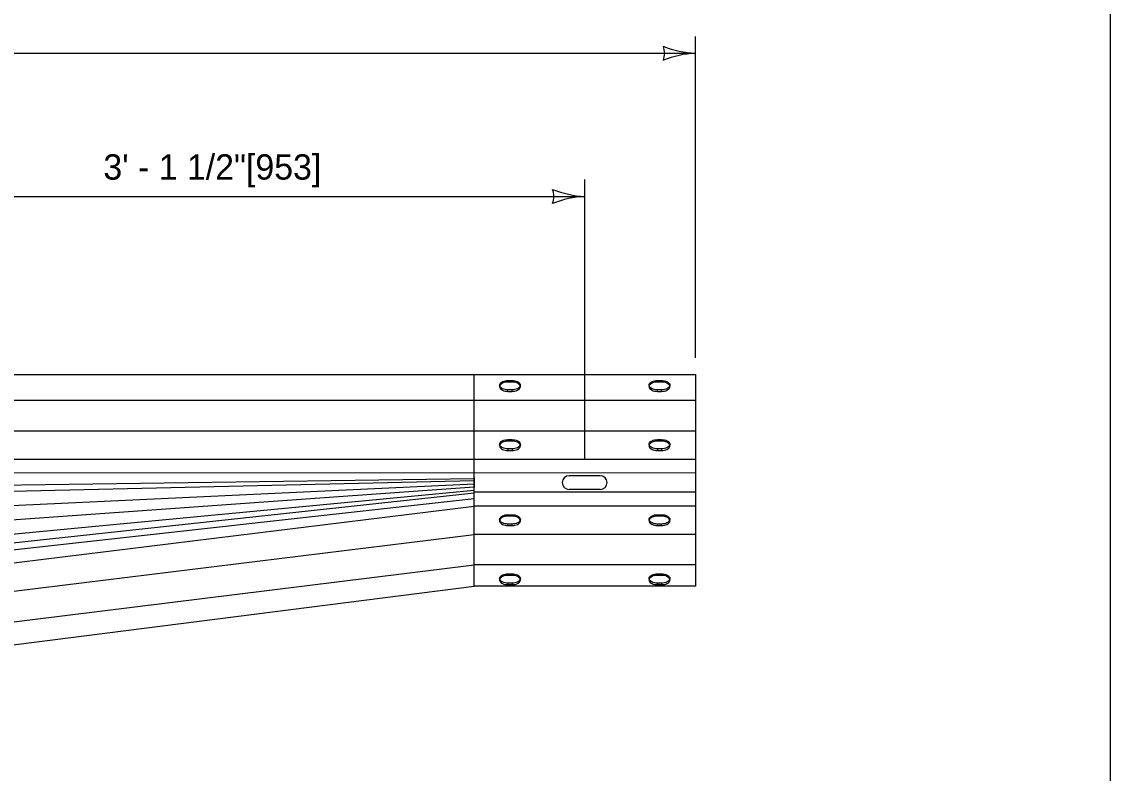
# Model space of a CAD drawing. Extents: x 49991 to 50160, y 49948 to 50051.
# Drawn here: x 50014.17 to 50016.75, y 49992.536 to 49994.318 of the extents above; entities that cross this region are included whole.
import ezdxf

# ---------------------------------------------------------------- set-up
doc = ezdxf.new("R2010")
doc.units = 0
for name, color, linetype in [('Level 1', 7, 'Continuous'), ('Level 2', 7, 'Continuous'), ('Level 3', 7, 'Continuous')]:
    doc.layers.add(name, color=color, linetype=linetype)

msp = doc.modelspace()

# ---------------------------------------------------------------- linework, layer by layer
at = {"layer": 'Level 1'}
for p, q in [((50012.234, 49993.4814), (50015.7668, 49993.4812)), ((50015.2419, 49992.9795), (50015.2419, 49993.4812)), ((50015.7668, 49993.4812), (50015.7668, 49993.4738)), ((50015.3025, 49993.4563), (50015.3025, 49993.4527)), ((50015.3222, 49993.4673), (50015.3321, 49993.4673)), ((50015.3222, 49993.4637), (50015.3222, 49993.4673)), ((50015.3321, 49993.4637), (50015.3222, 49993.4637)), ((50015.3321, 49993.4637), (50015.3321, 49993.4673)), ((50015.3518, 49993.4527), (50015.3518, 49993.4563)), ((50015.6569, 49993.4563), (50015.6569, 49993.4527)), ((50015.6766, 49993.4637), (50015.6766, 49993.4673)), ((50015.6766, 49993.4673), (50015.6864, 49993.4673)), ((50015.6864, 49993.4637), (50015.6766, 49993.4637)), ((50015.6864, 49993.4637), (50015.6864, 49993.4673)), ((50015.7061, 49993.4527), (50015.7061, 49993.4563)), ((50015.7668, 49993.4738), (50015.7668, 49993.471)), ((50015.7668, 49993.471), (50015.7668, 49993.4206)), ((50015.3321, 49993.4453), (50015.3222, 49993.4453)), ((50015.3222, 49993.4416), (50015.3222, 49993.4453)), ((50015.3222, 49993.4416), (50015.3321, 49993.4416)), ((50015.3321, 49993.4416), (50015.3321, 49993.4453)), ((50015.6864, 49993.4453), (50015.6766, 49993.4453)), ((50015.6766, 49993.4416), (50015.6766, 49993.4453)), ((50015.6766, 49993.4416), (50015.6864, 49993.4416)), ((50015.6864, 49993.4416), (50015.6864, 49993.4453)), ((50012.6417, 49993.4206), (50015.7668, 49993.4206)), ((50015.7668, 49993.4206), (50015.7668, 49993.3481)), ((50012.6417, 49993.3481), (50015.7668, 49993.3478)), ((50015.3222, 49993.3271), (50015.3321, 49993.3271)), ((50015.3222, 49993.3271), (50015.3222, 49993.3235)), ((50015.3321, 49993.3271), (50015.3321, 49993.3235)), ((50015.6766, 49993.3271), (50015.6864, 49993.3271)), ((50015.6766, 49993.3271), (50015.6766, 49993.3235)), ((50015.6864, 49993.3271), (50015.6864, 49993.3235)), ((50015.7668, 49993.3481), (50015.7668, 49993.2808)), ((50015.3025, 49993.3161), (50015.3025, 49993.3125)), ((50015.3321, 49993.3235), (50015.3222, 49993.3235)), ((50015.3222, 49993.3051), (50015.3222, 49993.3014)), ((50015.3321, 49993.3051), (50015.3222, 49993.3051)), ((50015.3222, 49993.3014), (50015.3321, 49993.3014)), ((50015.3321, 49993.3051), (50015.3321, 49993.3014)), ((50015.3518, 49993.3125), (50015.3518, 49993.3161)), ((50015.6569, 49993.3161), (50015.6569, 49993.3125)), ((50015.6864, 49993.3235), (50015.6766, 49993.3235)), ((50015.6766, 49993.3051), (50015.6766, 49993.3014)), ((50015.6864, 49993.3051), (50015.6766, 49993.3051)), ((50015.6766, 49993.3014), (50015.6864, 49993.3014)), ((50015.6864, 49993.3051), (50015.6864, 49993.3014)), ((50015.7061, 49993.3125), (50015.7061, 49993.3161)), ((50012.6417, 49993.2803), (50015.7668, 49993.2808)), ((50015.7668, 49993.2808), (50015.7668, 49993.2482)), ((50013.9811, 49993.2491), (50015.7668, 49993.2485)), ((50015.2419, 49993.2294), (50012.6417, 49993.1687)), ((50013.9757, 49993.2172), (50015.2419, 49993.2352)), ((50015.2419, 49993.2367), (50015.2419, 49993.2321)), ((50015.2419, 49993.2321), (50015.2419, 49993.2275)), ((50015.2419, 49993.2275), (50015.2419, 49993.223)), ((50015.2419, 49993.223), (50015.2419, 49993.2184)), ((50015.4674, 49993.2417), (50015.5412, 49993.2417)), ((50015.7668, 49993.2482), (50015.7668, 49993.2023)), ((50012.6417, 49993.1011), (50015.2419, 49993.2221)), ((50015.2419, 49993.2146), (50012.6417, 49993.0283)), ((50012.6417, 49992.9608), (50015.2419, 49993.2073)), ((50013.9883, 49993.0651), (50015.2419, 49993.201)), ((50015.2419, 49993.2184), (50015.2419, 49993.2138)), ((50015.7668, 49993.2023), (50015.2419, 49993.2023)), ((50015.5412, 49993.2088), (50015.4674, 49993.2088)), ((50015.7668, 49993.2023), (50015.7668, 49993.1697)), ((50013.9906, 49993.0485), (50015.2419, 49993.1879)), ((50012.6417, 49992.8492), (50015.2419, 49993.1697)), ((50015.7668, 49993.1697), (50015.2419, 49993.1697)), ((50015.3222, 49993.1491), (50015.3321, 49993.1491)), ((50015.3222, 49993.1454), (50015.3222, 49993.1491)), ((50015.3321, 49993.1454), (50015.3222, 49993.1454)), ((50015.3321, 49993.1454), (50015.3321, 49993.1491)), ((50015.6766, 49993.1491), (50015.6864, 49993.1491)), ((50015.6766, 49993.1454), (50015.6766, 49993.1491)), ((50015.6864, 49993.1454), (50015.6766, 49993.1454)), ((50015.6864, 49993.1454), (50015.6864, 49993.1491)), ((50015.7668, 49993.1697), (50015.7668, 49993.1024)), ((50015.3025, 49993.138), (50015.3025, 49993.1344)), ((50015.3321, 49993.127), (50015.3222, 49993.127)), ((50015.3222, 49993.1234), (50015.3222, 49993.127)), ((50015.3222, 49993.1234), (50015.3321, 49993.1234)), ((50015.3321, 49993.1234), (50015.3321, 49993.127)), ((50015.3518, 49993.1344), (50015.3518, 49993.138)), ((50015.6569, 49993.138), (50015.6569, 49993.1344)), ((50015.6864, 49993.127), (50015.6766, 49993.127)), ((50015.6766, 49993.1234), (50015.6766, 49993.127)), ((50015.6766, 49993.1234), (50015.6864, 49993.1234)), ((50015.6864, 49993.1234), (50015.6864, 49993.127)), ((50015.7061, 49993.1344), (50015.7061, 49993.138)), ((50012.6417, 49992.7816), (50015.2419, 49993.1024)), ((50015.7668, 49993.1024), (50015.2419, 49993.1024)), ((50015.7668, 49993.1024), (50015.7668, 49993.0299)), ((50012.6417, 49992.7088), (50015.2419, 49993.0299)), ((50015.7668, 49993.0299), (50015.2419, 49993.0299)), ((50015.7668, 49993.0299), (50015.7668, 49992.9795)), ((50015.3025, 49992.9978), (50015.3025, 49992.9942)), ((50015.3222, 49993.0089), (50015.3321, 49993.0089)), ((50015.3222, 49993.0089), (50015.3222, 49993.0052)), ((50015.3321, 49993.0052), (50015.3222, 49993.0052)), ((50015.3321, 49993.0089), (50015.3321, 49993.0052)), ((50015.3518, 49992.9942), (50015.3518, 49992.9978)), ((50015.6569, 49992.9978), (50015.6569, 49992.9942)), ((50015.6766, 49993.0089), (50015.6864, 49993.0089)), ((50015.6766, 49993.0089), (50015.6766, 49993.0052)), ((50015.6864, 49993.0052), (50015.6766, 49993.0052)), ((50015.6864, 49993.0089), (50015.6864, 49993.0052)), ((50015.7061, 49992.9942), (50015.7061, 49992.9978)), ((50012.6417, 49992.6481), (50015.2419, 49992.9795)), ((50015.7668, 49992.9795), (50015.2419, 49992.9795)), ((50015.3222, 49992.9868), (50015.3222, 49992.9832)), ((50015.3321, 49992.9868), (50015.3222, 49992.9868)), ((50015.3222, 49992.9832), (50015.3321, 49992.9832)), ((50015.3321, 49992.9868), (50015.3321, 49992.9832)), ((50015.6766, 49992.9868), (50015.6766, 49992.9832)), ((50015.6864, 49992.9868), (50015.6766, 49992.9868)), ((50015.6766, 49992.9832), (50015.6864, 49992.9832)), ((50015.6864, 49992.9868), (50015.6864, 49992.9832))]:
    msp.add_line(p, q, dxfattribs=at)
msp.add_lwpolyline([(49999.3835, 49998.9992), (50016.7501, 49998.9992), (50016.7501, 49987.7988), (49999.3835, 49987.7988)], close=True, dxfattribs=at)
for points in [[(50015.3222, 49993.4453), (50015.3188, 49993.4454), (50015.3155, 49993.4459), (50015.3124, 49993.4467), (50015.3096, 49993.4478), (50015.3072, 49993.4492), (50015.3052, 49993.4508), (50015.3037, 49993.4525), (50015.3028, 49993.4544), (50015.3025, 49993.4563), (50015.3028, 49993.4582), (50015.3037, 49993.4601), (50015.3052, 49993.4618), (50015.3072, 49993.4634), (50015.3096, 49993.4647), (50015.3124, 49993.4658), (50015.3155, 49993.4666), (50015.3188, 49993.4671), (50015.3222, 49993.4673)], [(50015.3222, 49993.4637), (50015.3188, 49993.4635), (50015.3155, 49993.463), (50015.3124, 49993.4622), (50015.3096, 49993.4611), (50015.3072, 49993.4597), (50015.3052, 49993.4582), (50015.3037, 49993.4564), (50015.3028, 49993.4546), (50015.3028, 49993.4545)], [(50015.3321, 49993.4673), (50015.3355, 49993.4671), (50015.3388, 49993.4666), (50015.3419, 49993.4658), (50015.3447, 49993.4647), (50015.3472, 49993.4634), (50015.3491, 49993.4618), (50015.3506, 49993.4601), (50015.3515, 49993.4582), (50015.3518, 49993.4563), (50015.3515, 49993.4544), (50015.3506, 49993.4525), (50015.3491, 49993.4508), (50015.3472, 49993.4492), (50015.3447, 49993.4478), (50015.3419, 49993.4467), (50015.3388, 49993.4459), (50015.3355, 49993.4454), (50015.3321, 49993.4453)], [(50015.3515, 49993.4545), (50015.3515, 49993.4546), (50015.3506, 49993.4564), (50015.3491, 49993.4582), (50015.3472, 49993.4597), (50015.3447, 49993.4611), (50015.3419, 49993.4622), (50015.3388, 49993.463), (50015.3355, 49993.4635), (50015.3321, 49993.4637)], [(50015.6766, 49993.4453), (50015.6731, 49993.4454), (50015.6698, 49993.4459), (50015.6667, 49993.4467), (50015.6639, 49993.4478), (50015.6615, 49993.4492), (50015.6595, 49993.4508), (50015.6581, 49993.4525), (50015.6572, 49993.4544), (50015.6569, 49993.4563), (50015.6572, 49993.4582), (50015.6581, 49993.4601), (50015.6595, 49993.4618), (50015.6615, 49993.4634), (50015.6639, 49993.4647), (50015.6667, 49993.4658), (50015.6698, 49993.4666), (50015.6731, 49993.4671), (50015.6766, 49993.4673)], [(50015.6766, 49993.4637), (50015.6731, 49993.4635), (50015.6698, 49993.463), (50015.6667, 49993.4622), (50015.6639, 49993.4611), (50015.6615, 49993.4597), (50015.6595, 49993.4582), (50015.6581, 49993.4564), (50015.6572, 49993.4546), (50015.6571, 49993.4545)], [(50015.6864, 49993.4673), (50015.6898, 49993.4671), (50015.6931, 49993.4666), (50015.6963, 49993.4658), (50015.6991, 49993.4647), (50015.7015, 49993.4634), (50015.7035, 49993.4618), (50015.7049, 49993.4601), (50015.7058, 49993.4582), (50015.7061, 49993.4563), (50015.7058, 49993.4544), (50015.7049, 49993.4525), (50015.7035, 49993.4508), (50015.7015, 49993.4492), (50015.6991, 49993.4478), (50015.6963, 49993.4467), (50015.6931, 49993.4459), (50015.6898, 49993.4454), (50015.6864, 49993.4453)], [(50015.7058, 49993.4545), (50015.7058, 49993.4546), (50015.7049, 49993.4564), (50015.7035, 49993.4582), (50015.7015, 49993.4597), (50015.6991, 49993.4611), (50015.6963, 49993.4622), (50015.6931, 49993.463), (50015.6898, 49993.4635), (50015.6864, 49993.4637)], [(50015.3028, 49993.4545), (50015.3025, 49993.4527), (50015.3028, 49993.4507), (50015.3037, 49993.4489), (50015.3052, 49993.4471), (50015.3072, 49993.4456), (50015.3096, 49993.4442), (50015.3124, 49993.4431), (50015.3155, 49993.4423), (50015.3188, 49993.4418), (50015.3222, 49993.4416)], [(50015.3321, 49993.4416), (50015.3355, 49993.4418), (50015.3388, 49993.4423), (50015.3419, 49993.4431), (50015.3447, 49993.4442), (50015.3472, 49993.4456), (50015.3491, 49993.4471), (50015.3506, 49993.4489), (50015.3515, 49993.4507), (50015.3518, 49993.4527), (50015.3515, 49993.4545)], [(50015.6571, 49993.4545), (50015.6569, 49993.4527), (50015.6572, 49993.4507), (50015.6581, 49993.4489), (50015.6595, 49993.4471), (50015.6615, 49993.4456), (50015.6639, 49993.4442), (50015.6667, 49993.4431), (50015.6698, 49993.4423), (50015.6731, 49993.4418), (50015.6766, 49993.4416)], [(50015.6864, 49993.4416), (50015.6898, 49993.4418), (50015.6931, 49993.4423), (50015.6963, 49993.4431), (50015.6991, 49993.4442), (50015.7015, 49993.4456), (50015.7035, 49993.4471), (50015.7049, 49993.4489), (50015.7058, 49993.4507), (50015.7061, 49993.4527), (50015.7058, 49993.4545)], [(50015.3028, 49993.3143), (50015.3025, 49993.3161), (50015.3028, 49993.318), (50015.3037, 49993.3199), (50015.3052, 49993.3216), (50015.3072, 49993.3232), (50015.3096, 49993.3245), (50015.3124, 49993.3256), (50015.3155, 49993.3264), (50015.3188, 49993.3269), (50015.3222, 49993.3271)], [(50015.3321, 49993.3271), (50015.3355, 49993.3269), (50015.3388, 49993.3264), (50015.3419, 49993.3256), (50015.3447, 49993.3245), (50015.3472, 49993.3232), (50015.3491, 49993.3216), (50015.3506, 49993.3199), (50015.3515, 49993.318), (50015.3518, 49993.3161), (50015.3515, 49993.3143)], [(50015.6571, 49993.3143), (50015.6569, 49993.3161), (50015.6572, 49993.318), (50015.6581, 49993.3199), (50015.6595, 49993.3216), (50015.6615, 49993.3232), (50015.6639, 49993.3245), (50015.6667, 49993.3256), (50015.6698, 49993.3264), (50015.6731, 49993.3269), (50015.6766, 49993.3271)], [(50015.6864, 49993.3271), (50015.6898, 49993.3269), (50015.6931, 49993.3264), (50015.6963, 49993.3256), (50015.6991, 49993.3245), (50015.7015, 49993.3232), (50015.7035, 49993.3216), (50015.7049, 49993.3199), (50015.7058, 49993.318), (50015.7061, 49993.3161), (50015.7058, 49993.3143)], [(50015.3222, 49993.3235), (50015.3188, 49993.3233), (50015.3155, 49993.3228), (50015.3124, 49993.322), (50015.3096, 49993.3209), (50015.3072, 49993.3195), (50015.3052, 49993.318), (50015.3037, 49993.3162), (50015.3028, 49993.3144), (50015.3025, 49993.3125), (50015.3028, 49993.3105), (50015.3037, 49993.3087), (50015.3052, 49993.3069), (50015.3072, 49993.3054), (50015.3096, 49993.304), (50015.3124, 49993.3029), (50015.3155, 49993.3021), (50015.3188, 49993.3016), (50015.3222, 49993.3014)], [(50015.3222, 49993.3051), (50015.3188, 49993.3052), (50015.3155, 49993.3057), (50015.3124, 49993.3065), (50015.3096, 49993.3076), (50015.3072, 49993.309), (50015.3052, 49993.3106), (50015.3037, 49993.3123), (50015.3028, 49993.3142), (50015.3028, 49993.3143)], [(50015.3321, 49993.3014), (50015.3355, 49993.3016), (50015.3388, 49993.3021), (50015.3419, 49993.3029), (50015.3447, 49993.304), (50015.3472, 49993.3054), (50015.3491, 49993.3069), (50015.3506, 49993.3087), (50015.3515, 49993.3105), (50015.3518, 49993.3125), (50015.3515, 49993.3144), (50015.3506, 49993.3162), (50015.3491, 49993.318), (50015.3472, 49993.3195), (50015.3447, 49993.3209), (50015.3419, 49993.322), (50015.3388, 49993.3228), (50015.3355, 49993.3233), (50015.3321, 49993.3235)], [(50015.3515, 49993.3143), (50015.3515, 49993.3142), (50015.3506, 49993.3123), (50015.3491, 49993.3106), (50015.3472, 49993.309), (50015.3447, 49993.3076), (50015.3419, 49993.3065), (50015.3388, 49993.3057), (50015.3355, 49993.3052), (50015.3321, 49993.3051)], [(50015.6766, 49993.3235), (50015.6731, 49993.3233), (50015.6698, 49993.3228), (50015.6667, 49993.322), (50015.6639, 49993.3209), (50015.6615, 49993.3195), (50015.6595, 49993.318), (50015.6581, 49993.3162), (50015.6572, 49993.3144), (50015.6569, 49993.3125), (50015.6572, 49993.3105), (50015.6581, 49993.3087), (50015.6595, 49993.3069), (50015.6615, 49993.3054), (50015.6639, 49993.304), (50015.6667, 49993.3029), (50015.6698, 49993.3021), (50015.6731, 49993.3016), (50015.6766, 49993.3014)], [(50015.6766, 49993.3051), (50015.6731, 49993.3052), (50015.6698, 49993.3057), (50015.6667, 49993.3065), (50015.6639, 49993.3076), (50015.6615, 49993.309), (50015.6595, 49993.3106), (50015.6581, 49993.3123), (50015.6572, 49993.3142), (50015.6571, 49993.3143)], [(50015.6864, 49993.3014), (50015.6898, 49993.3016), (50015.6931, 49993.3021), (50015.6963, 49993.3029), (50015.6991, 49993.304), (50015.7015, 49993.3054), (50015.7035, 49993.3069), (50015.7049, 49993.3087), (50015.7058, 49993.3105), (50015.7061, 49993.3125), (50015.7058, 49993.3144), (50015.7049, 49993.3162), (50015.7035, 49993.318), (50015.7015, 49993.3195), (50015.6991, 49993.3209), (50015.6963, 49993.322), (50015.6931, 49993.3228), (50015.6898, 49993.3233), (50015.6864, 49993.3235)], [(50015.7058, 49993.3143), (50015.7058, 49993.3142), (50015.7049, 49993.3123), (50015.7035, 49993.3106), (50015.7015, 49993.309), (50015.6991, 49993.3076), (50015.6963, 49993.3065), (50015.6931, 49993.3057), (50015.6898, 49993.3052), (50015.6864, 49993.3051)], [(50015.3222, 49993.127), (50015.3188, 49993.1272), (50015.3155, 49993.1277), (50015.3124, 49993.1285), (50015.3096, 49993.1296), (50015.3072, 49993.131), (50015.3052, 49993.1325), (50015.3037, 49993.1343), (50015.3028, 49993.1361), (50015.3025, 49993.138), (50015.3028, 49993.14), (50015.3037, 49993.1418), (50015.3052, 49993.1436), (50015.3072, 49993.1451), (50015.3096, 49993.1465), (50015.3124, 49993.1476), (50015.3155, 49993.1484), (50015.3188, 49993.1489), (50015.3222, 49993.1491)], [(50015.3222, 49993.1454), (50015.3188, 49993.1453), (50015.3155, 49993.1448), (50015.3124, 49993.144), (50015.3096, 49993.1429), (50015.3072, 49993.1415), (50015.3052, 49993.1399), (50015.3037, 49993.1382), (50015.3028, 49993.1363), (50015.3028, 49993.1362)], [(50015.3321, 49993.1491), (50015.3355, 49993.1489), (50015.3388, 49993.1484), (50015.3419, 49993.1476), (50015.3447, 49993.1465), (50015.3472, 49993.1451), (50015.3491, 49993.1436), (50015.3506, 49993.1418), (50015.3515, 49993.14), (50015.3518, 49993.138), (50015.3515, 49993.1361), (50015.3506, 49993.1343), (50015.3491, 49993.1325), (50015.3472, 49993.131), (50015.3447, 49993.1296), (50015.3419, 49993.1285), (50015.3388, 49993.1277), (50015.3355, 49993.1272), (50015.3321, 49993.127)], [(50015.3515, 49993.1362), (50015.3515, 49993.1363), (50015.3506, 49993.1382), (50015.3491, 49993.1399), (50015.3472, 49993.1415), (50015.3447, 49993.1429), (50015.3419, 49993.144), (50015.3388, 49993.1448), (50015.3355, 49993.1453), (50015.3321, 49993.1454)], [(50015.6766, 49993.127), (50015.6731, 49993.1272), (50015.6698, 49993.1277), (50015.6667, 49993.1285), (50015.6639, 49993.1296), (50015.6615, 49993.131), (50015.6595, 49993.1325), (50015.6581, 49993.1343), (50015.6572, 49993.1361), (50015.6569, 49993.138), (50015.6572, 49993.14), (50015.6581, 49993.1418), (50015.6595, 49993.1436), (50015.6615, 49993.1451), (50015.6639, 49993.1465), (50015.6667, 49993.1476), (50015.6698, 49993.1484), (50015.6731, 49993.1489), (50015.6766, 49993.1491)], [(50015.6766, 49993.1454), (50015.6731, 49993.1453), (50015.6698, 49993.1448), (50015.6667, 49993.144), (50015.6639, 49993.1429), (50015.6615, 49993.1415), (50015.6595, 49993.1399), (50015.6581, 49993.1382), (50015.6572, 49993.1363), (50015.6571, 49993.1362)], [(50015.6864, 49993.1491), (50015.6898, 49993.1489), (50015.6931, 49993.1484), (50015.6963, 49993.1476), (50015.6991, 49993.1465), (50015.7015, 49993.1451), (50015.7035, 49993.1436), (50015.7049, 49993.1418), (50015.7058, 49993.14), (50015.7061, 49993.138), (50015.7058, 49993.1361), (50015.7049, 49993.1343), (50015.7035, 49993.1325), (50015.7015, 49993.131), (50015.6991, 49993.1296), (50015.6963, 49993.1285), (50015.6931, 49993.1277), (50015.6898, 49993.1272), (50015.6864, 49993.127)], [(50015.7058, 49993.1362), (50015.7058, 49993.1363), (50015.7049, 49993.1382), (50015.7035, 49993.1399), (50015.7015, 49993.1415), (50015.6991, 49993.1429), (50015.6963, 49993.144), (50015.6931, 49993.1448), (50015.6898, 49993.1453), (50015.6864, 49993.1454)], [(50015.3028, 49993.1362), (50015.3025, 49993.1344), (50015.3028, 49993.1325), (50015.3037, 49993.1306), (50015.3052, 49993.1289), (50015.3072, 49993.1273), (50015.3096, 49993.126), (50015.3124, 49993.1249), (50015.3155, 49993.1241), (50015.3188, 49993.1236), (50015.3222, 49993.1234)], [(50015.3321, 49993.1234), (50015.3355, 49993.1236), (50015.3388, 49993.1241), (50015.3419, 49993.1249), (50015.3447, 49993.126), (50015.3472, 49993.1273), (50015.3491, 49993.1289), (50015.3506, 49993.1306), (50015.3515, 49993.1325), (50015.3518, 49993.1344), (50015.3515, 49993.1362)], [(50015.6571, 49993.1362), (50015.6569, 49993.1344), (50015.6572, 49993.1325), (50015.6581, 49993.1306), (50015.6595, 49993.1289), (50015.6615, 49993.1273), (50015.6639, 49993.126), (50015.6667, 49993.1249), (50015.6698, 49993.1241), (50015.6731, 49993.1236), (50015.6766, 49993.1234)], [(50015.6864, 49993.1234), (50015.6898, 49993.1236), (50015.6931, 49993.1241), (50015.6963, 49993.1249), (50015.6991, 49993.126), (50015.7015, 49993.1273), (50015.7035, 49993.1289), (50015.7049, 49993.1306), (50015.7058, 49993.1325), (50015.7061, 49993.1344), (50015.7058, 49993.1362)], [(50015.3028, 49992.996), (50015.3025, 49992.9978), (50015.3028, 49992.9998), (50015.3037, 49993.0016), (50015.3052, 49993.0034), (50015.3072, 49993.0049), (50015.3096, 49993.0063), (50015.3124, 49993.0074), (50015.3155, 49993.0082), (50015.3188, 49993.0087), (50015.3222, 49993.0089)], [(50015.3222, 49993.0052), (50015.3188, 49993.0051), (50015.3155, 49993.0046), (50015.3124, 49993.0038), (50015.3096, 49993.0027), (50015.3072, 49993.0013), (50015.3052, 49992.9997), (50015.3037, 49992.998), (50015.3028, 49992.9961), (50015.3025, 49992.9942), (50015.3028, 49992.9923), (50015.3037, 49992.9904), (50015.3052, 49992.9887), (50015.3072, 49992.9871), (50015.3096, 49992.9858), (50015.3124, 49992.9847), (50015.3155, 49992.9839), (50015.3188, 49992.9834), (50015.3222, 49992.9832)], [(50015.3222, 49992.9868), (50015.3188, 49992.987), (50015.3155, 49992.9875), (50015.3124, 49992.9883), (50015.3096, 49992.9894), (50015.3072, 49992.9908), (50015.3052, 49992.9923), (50015.3037, 49992.9941), (50015.3028, 49992.9959), (50015.3028, 49992.996)], [(50015.3321, 49993.0089), (50015.3355, 49993.0087), (50015.3388, 49993.0082), (50015.3419, 49993.0074), (50015.3447, 49993.0063), (50015.3472, 49993.0049), (50015.3491, 49993.0034), (50015.3506, 49993.0016), (50015.3515, 49992.9998), (50015.3518, 49992.9978), (50015.3515, 49992.996)], [(50015.3321, 49992.9832), (50015.3355, 49992.9834), (50015.3388, 49992.9839), (50015.3419, 49992.9847), (50015.3447, 49992.9858), (50015.3472, 49992.9871), (50015.3491, 49992.9887), (50015.3506, 49992.9904), (50015.3515, 49992.9923), (50015.3518, 49992.9942), (50015.3515, 49992.9961), (50015.3506, 49992.998), (50015.3491, 49992.9997), (50015.3472, 49993.0013), (50015.3447, 49993.0027), (50015.3419, 49993.0038), (50015.3388, 49993.0046), (50015.3355, 49993.0051), (50015.3321, 49993.0052)], [(50015.3515, 49992.996), (50015.3515, 49992.9959), (50015.3506, 49992.9941), (50015.3491, 49992.9923), (50015.3472, 49992.9908), (50015.3447, 49992.9894), (50015.3419, 49992.9883), (50015.3388, 49992.9875), (50015.3355, 49992.987), (50015.3321, 49992.9868)], [(50015.6571, 49992.996), (50015.6569, 49992.9978), (50015.6572, 49992.9998), (50015.6581, 49993.0016), (50015.6595, 49993.0034), (50015.6615, 49993.0049), (50015.6639, 49993.0063), (50015.6667, 49993.0074), (50015.6698, 49993.0082), (50015.6731, 49993.0087), (50015.6766, 49993.0089)], [(50015.6766, 49993.0052), (50015.6731, 49993.0051), (50015.6698, 49993.0046), (50015.6667, 49993.0038), (50015.6639, 49993.0027), (50015.6615, 49993.0013), (50015.6595, 49992.9997), (50015.6581, 49992.998), (50015.6572, 49992.9961), (50015.6569, 49992.9942), (50015.6572, 49992.9923), (50015.6581, 49992.9904), (50015.6595, 49992.9887), (50015.6615, 49992.9871), (50015.6639, 49992.9858), (50015.6667, 49992.9847), (50015.6698, 49992.9839), (50015.6731, 49992.9834), (50015.6766, 49992.9832)], [(50015.6766, 49992.9868), (50015.6731, 49992.987), (50015.6698, 49992.9875), (50015.6667, 49992.9883), (50015.6639, 49992.9894), (50015.6615, 49992.9908), (50015.6595, 49992.9923), (50015.6581, 49992.9941), (50015.6572, 49992.9959), (50015.6571, 49992.996)], [(50015.6864, 49993.0089), (50015.6898, 49993.0087), (50015.6931, 49993.0082), (50015.6963, 49993.0074), (50015.6991, 49993.0063), (50015.7015, 49993.0049), (50015.7035, 49993.0034), (50015.7049, 49993.0016), (50015.7058, 49992.9998), (50015.7061, 49992.9978), (50015.7058, 49992.996)], [(50015.6864, 49992.9832), (50015.6898, 49992.9834), (50015.6931, 49992.9839), (50015.6963, 49992.9847), (50015.6991, 49992.9858), (50015.7015, 49992.9871), (50015.7035, 49992.9887), (50015.7049, 49992.9904), (50015.7058, 49992.9923), (50015.7061, 49992.9942), (50015.7058, 49992.9961), (50015.7049, 49992.998), (50015.7035, 49992.9997), (50015.7015, 49993.0013), (50015.6991, 49993.0027), (50015.6963, 49993.0038), (50015.6931, 49993.0046), (50015.6898, 49993.0051), (50015.6864, 49993.0052)], [(50015.7058, 49992.996), (50015.7058, 49992.9959), (50015.7049, 49992.9941), (50015.7035, 49992.9923), (50015.7015, 49992.9908), (50015.6991, 49992.9894), (50015.6963, 49992.9883), (50015.6931, 49992.9875), (50015.6898, 49992.987), (50015.6864, 49992.9868)]]:
    msp.add_lwpolyline(points, dxfattribs=at)
for centre, start, end in [((50015.4674, 49993.2252), 90, 270), ((50015.5412, 49993.2252), 270, 90)]:
    msp.add_arc(centre, 0.0164, start, end, dxfattribs=at)
at = {"layer": 'Level 3'}
for p, q in [((50015.7668, 49993.5212), (50015.7668, 49994.2833)), ((50012.1168, 49994.2433), (50015.7668, 49994.2433)), ((50015.5043, 49993.2817), (50015.5043, 49993.9437)), ((50013.9388, 49993.9037), (50015.5043, 49993.9037))]:
    msp.add_line(p, q, dxfattribs=at)
for centre, radius, start, end in [((50015.7759, 49994.4654), 0.2223, 247.456, 267.6395), ((50015.6386, 49994.2433), 0.0548, 342.1388, 17.8612), ((50015.7783, 49994.0106), 0.233, 92.8273, 112.0772), ((50015.5135, 49994.1259), 0.2223, 247.456, 267.6395), ((50015.3761, 49993.9037), 0.0548, 342.1388, 17.8612), ((50015.5158, 49993.671), 0.233, 92.8273, 112.0772)]:
    msp.add_arc(centre, radius, start, end, dxfattribs=at)

# ---------------------------------------------------------------- texts
at = {"layer": 'Level 2'}
msp.add_text('3\' - 1 1/2"[953]', height=0.06, dxfattribs=at).set_placement((50014.3632, 49993.9437))

doc.saveas('drawing.dxf')
